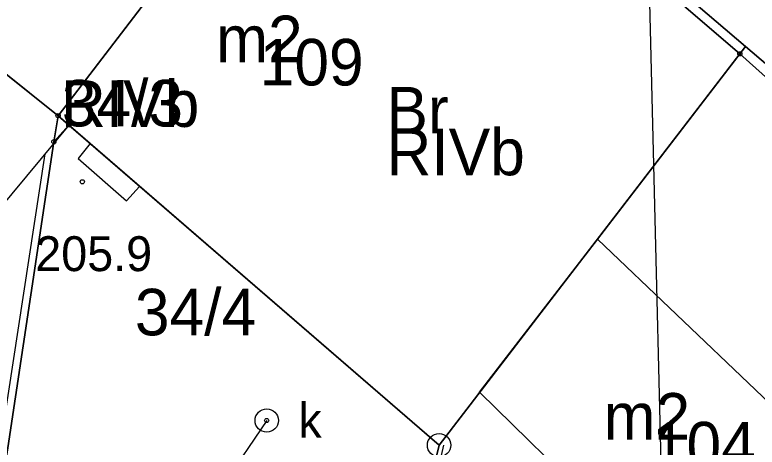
# Model space of a CAD drawing. Extents: x 6512606 to 6513006, y 6022524 to 6022728.
# Drawn here: x 6512794.61 to 6512810.55, y 6022654.83 to 6022664.12 of the extents above; entities that cross this region are included whole.
import ezdxf

# ---------------------------------------------------------------- set-up
doc = ezdxf.new("R2010")
doc.units = 0
for name, color, linetype in [('202-punkt graniczny', 7, 'Continuous'), ('203-punkt graniczny', 7, 'Continuous'), ('209-oznaczenie konturu klasyfikacyjnego', 7, 'Continuous'), ('210-oznaczenie konturu użytku gruntowego', 7, 'Continuous'), ('211-numer działki ewidencyjnej', 7, 'Continuous'), ('216-obręb ewidencyjny', 7, 'Continuous'), ('217-kontur klasyfikacyjny', 7, 'Continuous'), ('218-kontur użytku gruntowego', 7, 'Continuous'), ('219-działka ewidencyjna', 7, 'Continuous'), ('312-budynek ewidencyjny', 7, 'Continuous'), ('312-oznaczenie budynku ewidencyjnego', 7, 'Continuous'), ('312-oznaczenie budynku ewidencyjnego-Atr117', 7, 'Continuous'), ('356-Świetlik', 7, 'Continuous'), ('4', 7, 'Continuous'), ('chodnik (powierzchnia)', 7, 'Continuous'), ('Default', 7, 'Continuous'), ('Obszar opracowania', 7, 'Continuous'), ('ogrodzenie trwałe', 7, 'Continuous'), ('punkt o określonej wysokości (sieć kanalizacyjna)', 7, 'Continuous'), ('punkt o określonej wysokości (sieć kanalizacyjna)-Atr2', 7, 'Continuous'), ('punkt wysokościowy naturalny', 7, 'Continuous'), ('punkt wysokościowy naturalny-Atr2', 7, 'Continuous'), ('właz okrągły - siec kanalizacyjna (punkt)', 7, 'Continuous'), ('właz okrągły - siec kanalizacyjna (punkt)-Atr17', 7, 'Continuous')]:
    doc.layers.add(name, color=color, linetype=linetype)

# ---------------------------------------------------------------- blocks, each defined once
blk = doc.blocks.new('203')
at = {"layer": 'Default'}
blk.add_circle((0, 0), 0.45, dxfattribs=at)
blk = doc.blocks.new('202')
at = {"layer": 'Default'}
blk.add_circle((0, 0), 2.5, dxfattribs=at)
blk = doc.blocks.new('PW01')
at = {"layer": 'Default'}
blk.add_circle((0, 0), 0.45, dxfattribs=at)
blk = doc.blocks.new('US22')
at = {"layer": 'Default'}
blk.add_circle((0, 0), 2.5, dxfattribs=at)

msp = doc.modelspace()

# ---------------------------------------------------------------- linework, layer by layer
at = {"layer": '216-obręb ewidencyjny'}
for points in [[(6512836.687, 6022675.173), (6512833.61, 6022675.02), (6512828.67, 6022670.98), (6512801.96, 6022670.34), (6512810.18, 6022663.28), (6512825.37, 6022649.66), (6512838.47, 6022634.29), (6512852.25, 6022608.25), (6512853.17, 6022604.51), (6512855.78, 6022583.95), (6512858.85, 6022571.74), (6512828.23, 6022562.62), (6512818.47, 6022559.72), (6512824.714, 6022553.406)], [(6512852.25, 6022608.25), (6512838.47, 6022634.29), (6512825.37, 6022649.66), (6512810.18, 6022663.28), (6512801.96, 6022670.34), (6512796.96, 6022674.74), (6512790.49, 6022674.74), (6512785.56, 6022674.74), (6512768.24, 6022674.27), (6512754.87, 6022673.72), (6512745.51, 6022673.33), (6512735.76, 6022672.94), (6512730.35, 6022672.71), (6512725.78, 6022672.95), (6512702.575, 6022674.177)]]:
    msp.add_lwpolyline(points, dxfattribs=at)
at = {"layer": '217-kontur klasyfikacyjny'}
for points in [[(6512801.96, 6022670.34), (6512795.54, 6022661.95)], [(6512810.18, 6022663.28), (6512801.96, 6022670.34)], [(6512795.54, 6022661.95), (6512786.09, 6022669.52)], [(6512803.72, 6022654.87), (6512810.18, 6022663.28)], [(6512795.54, 6022661.95), (6512795.45, 6022661.39)], [(6512795.45, 6022661.39), (6512795.54, 6022661.95)], [(6512795.77, 6022661.75), (6512795.54, 6022661.95)], [(6512795.54, 6022661.95), (6512795.77, 6022661.75)], [(6512795.77, 6022661.75), (6512795.45, 6022661.39)], [(6512795.45, 6022661.39), (6512795.77, 6022661.75)], [(6512803.72, 6022654.87), (6512795.77, 6022661.75)], [(6512795.77, 6022661.75), (6512803.72, 6022654.87)], [(6512795.45, 6022661.39), (6512792.46, 6022641.52)], [(6512792.46, 6022641.52), (6512795.45, 6022661.39)], [(6512802.13, 6022648.24), (6512803.72, 6022654.87)]]:
    msp.add_lwpolyline(points, dxfattribs=at)
at = {"layer": '218-kontur użytku gruntowego'}
for points in [[(6512801.96, 6022670.34), (6512795.54, 6022661.95)], [(6512795.54, 6022661.95), (6512801.96, 6022670.34)], [(6512810.18, 6022663.28), (6512801.96, 6022670.34)], [(6512801.96, 6022670.34), (6512810.18, 6022663.28)], [(6512795.54, 6022661.95), (6512786.09, 6022669.52)], [(6512786.09, 6022669.52), (6512795.54, 6022661.95)], [(6512803.72, 6022654.87), (6512810.18, 6022663.28)], [(6512810.18, 6022663.28), (6512803.72, 6022654.87)], [(6512825.37, 6022649.66), (6512810.18, 6022663.28)], [(6512810.18, 6022663.28), (6512825.37, 6022649.66)], [(6512795.54, 6022661.95), (6512795.45, 6022661.39)], [(6512795.45, 6022661.39), (6512795.54, 6022661.95)], [(6512795.77, 6022661.75), (6512795.54, 6022661.95)], [(6512795.54, 6022661.95), (6512795.77, 6022661.75)], [(6512795.77, 6022661.75), (6512795.45, 6022661.39)], [(6512795.45, 6022661.39), (6512795.77, 6022661.75)], [(6512803.72, 6022654.87), (6512795.77, 6022661.75)], [(6512795.77, 6022661.75), (6512803.72, 6022654.87)], [(6512795.45, 6022661.39), (6512792.46, 6022641.52)], [(6512792.46, 6022641.52), (6512795.45, 6022661.39)], [(6512802.13, 6022648.24), (6512803.72, 6022654.87)], [(6512803.72, 6022654.87), (6512802.13, 6022648.24)]]:
    msp.add_lwpolyline(points, dxfattribs=at)
at = {"layer": '219-działka ewidencyjna'}
for points in [[(6512801.96, 6022670.34), (6512795.54, 6022661.95)], [(6512801.96, 6022670.34), (6512810.18, 6022663.28)], [(6512810.18, 6022663.28), (6512803.72, 6022654.87)], [(6512825.37, 6022649.66), (6512810.18, 6022663.28)], [(6512795.54, 6022661.95), (6512795.45, 6022661.39)], [(6512795.77, 6022661.75), (6512795.54, 6022661.95)], [(6512795.77, 6022661.75), (6512795.45, 6022661.39)], [(6512803.72, 6022654.87), (6512795.77, 6022661.75)], [(6512795.45, 6022661.39), (6512792.46, 6022641.52)], [(6512803.72, 6022654.87), (6512802.13, 6022648.24)]]:
    msp.add_lwpolyline(points, dxfattribs=at)
at = {"layer": '312-budynek ewidencyjny'}
for points in [[(6512795.54, 6022661.95), (6512802.06, 6022670.47)], [(6512802.06, 6022670.47), (6512795.54, 6022661.95)], [(6512802.06, 6022670.47), (6512810.3, 6022663.44)], [(6512795.54, 6022661.95), (6512789.92, 6022666.46)], [(6512789.92, 6022666.46), (6512795.54, 6022661.95)], [(6512810.3, 6022663.44), (6512807.12, 6022659.3)], [(6512807.12, 6022659.3), (6512810.3, 6022663.44)], [(6512810.3, 6022663.44), (6512816.1, 6022658.5)], [(6512803.72, 6022654.87), (6512795.54, 6022661.95)], [(6512795.77, 6022661.75), (6512787.51, 6022651.8)], [(6512804.59, 6022656.01), (6512807.12, 6022659.3)], [(6512807.12, 6022659.3), (6512804.59, 6022656.01)], [(6512807.12, 6022659.3), (6512812.21, 6022654.44)], [(6512812.21, 6022654.44), (6512807.12, 6022659.3)], [(6512804.59, 6022656.01), (6512803.72, 6022654.87)], [(6512809.53, 6022651.17), (6512804.59, 6022656.01)]]:
    msp.add_lwpolyline(points, dxfattribs=at)
at = {"layer": '356-Świetlik'}
msp.add_lwpolyline([(6512796.23, 6022661.35), (6512795.97, 6022661.03), (6512797.01, 6022660.12), (6512797.29, 6022660.43)], close=True, dxfattribs=at)
at = {"layer": '4'}
for points in [[(6512801.96, 6022670.34), (6512795.54, 6022661.95)], [(6512801.96, 6022670.34), (6512810.18, 6022663.28)], [(6512810.18, 6022663.28), (6512803.72, 6022654.87)], [(6512825.37, 6022649.66), (6512810.18, 6022663.28)], [(6512795.54, 6022661.95), (6512795.45, 6022661.39)], [(6512795.77, 6022661.75), (6512795.54, 6022661.95)], [(6512795.77, 6022661.75), (6512795.45, 6022661.39)], [(6512803.72, 6022654.87), (6512795.77, 6022661.75)], [(6512795.45, 6022661.39), (6512792.46, 6022641.52)], [(6512803.72, 6022654.87), (6512802.13, 6022648.24)]]:
    msp.add_lwpolyline(points, dxfattribs=at)
at = {"layer": 'chodnik (powierzchnia)'}
msp.add_lwpolyline([(6512845.61, 6022610.5), (6512844.69, 6022613.44), (6512844.06, 6022613.28), (6512843.41, 6022615.01), (6512844.01, 6022615.23), (6512838.87, 6022629.83), (6512839.52, 6022630.32), (6512838.94, 6022631.84), (6512838.15, 6022631.88), (6512837.86, 6022632.79), (6512838.13, 6022633.96), (6512826.89, 6022646.81), (6512825.11, 6022648.85), (6512824.32, 6022649.76), (6512820.29, 6022654.03), (6512817.62, 6022656.88), (6512816.1, 6022658.5), (6512810.3, 6022663.44), (6512802.06, 6022670.47), (6512797.05, 6022674.74)], dxfattribs=at)
at = {"layer": 'Obszar opracowania'}
msp.add_lwpolyline([(6512710.98, 6022693.84), (6512748.35, 6022694.16), (6512798.11, 6022695.25), (6512807.47, 6022695.46), (6512809.66, 6022606.87), (6512863.71, 6022622.03), (6512875.13, 6022581.36), (6512755.22, 6022535.25), (6512691.61, 6022568.03), (6512709.16, 6022605.16)], close=True, dxfattribs=at)
at = {"layer": 'ogrodzenie trwałe'}
for points in [[(6512794, 6022652.94), (6512795.26, 6022661.13)], [(6512803.32, 6022652.64), (6512803.82, 6022654.87)]]:
    msp.add_lwpolyline(points, dxfattribs=at)
at = {"layer": 'punkt o określonej wysokości (sieć kanalizacyjna)-Atr2'}
msp.add_lwpolyline([(6512800.02, 6022655.4), (6512799.1, 6022654.04), (6512795.959, 6022654.04)], dxfattribs=at)

# ---------------------------------------------------------------- block references
at = {"layer": '202-punkt graniczny', "xscale": 0.1, "yscale": 0.10000000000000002}
msp.add_blockref('202', (6512803.72, 6022654.87), dxfattribs=at)
at = {"layer": '203-punkt graniczny', "xscale": 0.1, "yscale": 0.10000000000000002}
for p in [(6512810.18, 6022663.28), (6512795.54, 6022661.95), (6512795.77, 6022661.75), (6512795.45, 6022661.39)]:
    msp.add_blockref('203', p, dxfattribs=at)
at = {"layer": 'punkt o określonej wysokości (sieć kanalizacyjna)', "xscale": 0.1, "yscale": 0.10000000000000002}
msp.add_blockref('PW01', (6512800.02, 6022655.4), dxfattribs=at)
at = {"layer": 'punkt wysokościowy naturalny', "xscale": 0.1, "yscale": 0.10000000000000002}
msp.add_blockref('PW01', (6512796.06, 6022660.53), dxfattribs=at)
at = {"layer": 'właz okrągły - siec kanalizacyjna (punkt)', "xscale": 0.1, "yscale": 0.10000000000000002}
msp.add_blockref('US22', (6512800.02, 6022655.4), dxfattribs=at)

# ---------------------------------------------------------------- texts
at = {"layer": '209-oznaczenie konturu klasyfikacyjnego'}
for p in [(6512795.6, 6022661.71), (6512802.59, 6022660.67)]:
    msp.add_text('RIVb', height=1, dxfattribs=at).set_placement(p)
at = {"layer": '210-oznaczenie konturu użytku gruntowego'}
for s, p in [('R', (6512795.6, 6022661.71)), ('Br', (6512802.59, 6022661.57))]:
    msp.add_text(s, height=1, dxfattribs=at).set_placement(p)
at = {"layer": '211-numer działki ewidencyjnej'}
for s, p in [('34/3', (6512795.62, 6022661.72)), ('34/4', (6512797.19, 6022657.23))]:
    msp.add_text(s, height=1, dxfattribs=at).set_placement(p)
at = {"layer": '312-oznaczenie budynku ewidencyjnego'}
for s, p in [('109', (6512799.87, 6022662.6)), ('104', (6512808.29, 6022654.37))]:
    msp.add_text(s, height=1, dxfattribs=at).set_placement(p)
at = {"layer": '312-oznaczenie budynku ewidencyjnego-Atr117'}
for p in [(6512798.935, 6022663.1), (6512807.255, 6022654.99)]:
    msp.add_text('m2', height=1, dxfattribs=at).set_placement(p)
at = {"layer": '4'}
for s, p in [('34/3', (6512795.62, 6022661.72)), ('34/4', (6512797.19, 6022657.23))]:
    msp.add_text(s, height=1, dxfattribs=at).set_placement(p)
at = {"layer": 'punkt wysokościowy naturalny-Atr2'}
msp.add_text('205.9', height=0.75, dxfattribs=at).set_placement((6512795.05, 6022658.61))
at = {"layer": 'właz okrągły - siec kanalizacyjna (punkt)-Atr17'}
msp.add_text('k', height=0.75, dxfattribs=at).set_placement((6512800.7, 6022655.03))

doc.saveas('drawing.dxf')
